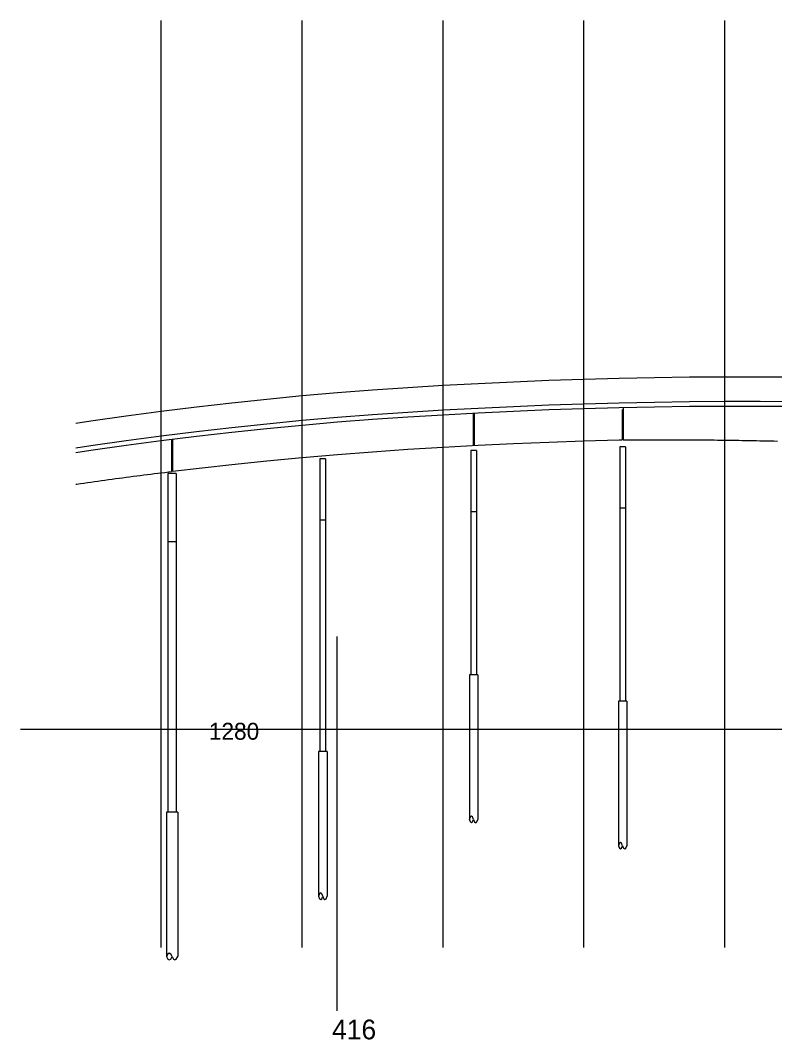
# Model space of a CAD drawing. Extents: x 2144454 to 2150191, y 137247 to 142100.
# Drawn here: x 2144454 to 2144990, y 137323 to 138047 of the extents above; entities that cross this region are included whole.
import ezdxf

# ---------------------------------------------------------------- set-up
doc = ezdxf.new("R2010")
doc.units = 0
for name, color, linetype in [('FinGrade', 7, 'Continuous'), ('PR_Bridge', 7, 'Continuous'), ('PR_Bridge_Pier', 7, 'Continuous'), ('XSEC_Section_Grid_Major', 7, 'Continuous')]:
    doc.layers.add(name, color=color, linetype=linetype)

msp = doc.modelspace()

# ---------------------------------------------------------------- linework, layer by layer
at = {"layer": 'Defpoints'}
for p, q in [((2144679.13, 137343.65), (2144679.13, 137609.38)), ((2144454.23, 137543.65), (2145154.23, 137543.65)), ((2144590.07, 137543.65), (2144690.59, 137543.65))]:
    msp.add_line(p, q, dxfattribs=at)
at = {"layer": 'FinGrade'}
for p, q in [((2144829.23, 137773.75), (2144854.23, 137774.6)), ((2144854.23, 137774.6), (2144879.23, 137775.28)), ((2144879.23, 137775.28), (2144904.23, 137775.79)), ((2144904.23, 137775.79), (2144929.23, 137776.13)), ((2144929.23, 137776.13), (2144954.23, 137776.3)), ((2144954.23, 137776.3), (2144979.23, 137776.3)), ((2144979.23, 137776.3), (2145004.23, 137776.13)), ((2144679.23, 137764.98), (2144704.23, 137766.9)), ((2144704.23, 137766.9), (2144729.23, 137768.62)), ((2144729.23, 137768.62), (2144754.23, 137770.16)), ((2144754.23, 137770.16), (2144779.23, 137771.53)), ((2144779.23, 137771.53), (2144804.23, 137772.72)), ((2144804.23, 137772.72), (2144829.23, 137773.75)), ((2144604.23, 137757.81), (2144629.23, 137760.44)), ((2144629.23, 137760.44), (2144654.23, 137762.83)), ((2144654.23, 137762.83), (2144679.23, 137764.98)), ((2144554.23, 137751.86), (2144579.23, 137754.95)), ((2144579.23, 137754.95), (2144604.23, 137757.81)), ((2144504.23, 137744.94), (2144529.23, 137748.52)), ((2144529.23, 137748.52), (2144554.23, 137751.86)), ((2144493.6, 137743.35), (2144504.23, 137744.94))]:
    msp.add_line(p, q, dxfattribs=at)
at = {"layer": 'PR_Bridge'}
for p, q in [((2144754.23, 137787.66), (2144779.23, 137789.03)), ((2144779.23, 137789.03), (2144804.23, 137790.22)), ((2144804.23, 137790.22), (2144829.23, 137791.25)), ((2144829.23, 137791.25), (2144854.23, 137792.1)), ((2144854.23, 137792.1), (2144879.23, 137792.78)), ((2144879.23, 137792.78), (2144904.23, 137793.29)), ((2144904.23, 137793.29), (2144929.23, 137793.63)), ((2144929.23, 137793.63), (2144954.23, 137793.8)), ((2144954.23, 137793.8), (2144979.23, 137793.8)), ((2144979.23, 137793.8), (2145004.23, 137793.63)), ((2144654.23, 137780.33), (2144679.23, 137782.48)), ((2144679.23, 137782.48), (2144704.23, 137784.4)), ((2144704.23, 137784.4), (2144729.23, 137786.12)), ((2144729.23, 137786.12), (2144754.23, 137787.66)), ((2144579.23, 137772.45), (2144604.23, 137775.31)), ((2144604.23, 137775.31), (2144629.23, 137777.94)), ((2144629.23, 137777.94), (2144654.23, 137780.33)), ((2144529.23, 137766.02), (2144554.23, 137769.36)), ((2144554.23, 137769.36), (2144579.23, 137772.45)), ((2144729.23, 137765.29), (2144754.23, 137766.83)), ((2144754.23, 137766.83), (2144779.23, 137768.2)), ((2144775.55, 137768.08), (2144775.55, 137744.99)), ((2144776.22, 137768.02), (2144776.22, 137745.03)), ((2144779.23, 137768.2), (2144804.23, 137769.39)), ((2144804.23, 137769.39), (2144829.23, 137770.42)), ((2144829.23, 137770.42), (2144854.23, 137771.27)), ((2144854.23, 137771.27), (2144879.23, 137771.95)), ((2144879.23, 137771.95), (2144904.23, 137772.46)), ((2144881.34, 137770.6), (2144881.34, 137748.94)), ((2144882.01, 137772), (2144882.01, 137748.97)), ((2144904.23, 137772.46), (2144929.23, 137772.79)), ((2144929.23, 137772.79), (2144954.23, 137772.96)), ((2144954.23, 137772.96), (2144979.23, 137772.96)), ((2144979.23, 137772.96), (2145004.23, 137772.79)), ((2144493.6, 137760.85), (2144504.23, 137762.44)), ((2144504.23, 137762.44), (2144529.23, 137766.02)), ((2144629.23, 137757.11), (2144654.23, 137759.49)), ((2144654.23, 137759.49), (2144679.23, 137761.65)), ((2144679.23, 137761.65), (2144704.23, 137763.57)), ((2144704.23, 137763.57), (2144729.23, 137765.29)), ((2144579.23, 137751.62), (2144604.23, 137754.48)), ((2144604.23, 137754.48), (2144629.23, 137757.11)), ((2144504.23, 137741.61), (2144529.23, 137745.19)), ((2144529.23, 137745.19), (2144554.23, 137748.52)), ((2144554.23, 137748.52), (2144579.23, 137751.62)), ((2144561.55, 137749.42), (2144561.55, 137726.46)), ((2144562.22, 137749.51), (2144562.22, 137726.54)), ((2144754.23, 137743.83), (2144779.23, 137745.19)), ((2144779.23, 137745.19), (2144804.23, 137746.39)), ((2144804.23, 137746.39), (2144829.23, 137747.41)), ((2144829.23, 137747.41), (2144854.23, 137748.26)), ((2144854.23, 137748.26), (2144879.23, 137748.94)), ((2144879.23, 137748.94), (2144881.34, 137748.99)), ((2144493.6, 137740.02), (2144504.23, 137741.61)), ((2144654.23, 137736.49), (2144679.23, 137738.65)), ((2144679.23, 137738.65), (2144704.23, 137740.57)), ((2144704.23, 137740.57), (2144729.23, 137742.28)), ((2144729.23, 137742.28), (2144754.23, 137743.83)), ((2144562.22, 137726.67), (2144604.23, 137731.48)), ((2144604.23, 137731.48), (2144629.23, 137734.1)), ((2144629.23, 137734.1), (2144654.23, 137736.49))]:
    msp.add_line(p, q, dxfattribs=at)
for points in [[(2144882.01, 137748.97), (2144884.14, 137748.98), (2144886.63, 137749), (2144889.13, 137749.02), (2144891.63, 137749.03), (2144894.13, 137749.04), (2144896.63, 137749.05), (2144899.13, 137749.06), (2144901.63, 137749.07), (2144904.13, 137749.07), (2144906.63, 137749.08), (2144909.13, 137749.08), (2144911.63, 137749.08), (2144914.13, 137749.08), (2144916.63, 137749.07), (2144919.12, 137749.06), (2144921.62, 137749.06), (2144924.12, 137749.05), (2144926.62, 137749.04), (2144929.12, 137749.02), (2144931.62, 137749.01), (2144934.12, 137748.99), (2144936.62, 137748.97), (2144939.12, 137748.95), (2144941.62, 137748.93), (2144944.12, 137748.9), (2144946.62, 137748.88), (2144949.11, 137748.85), (2144951.61, 137748.82), (2144954.11, 137748.79), (2144956.61, 137748.75), (2144959.11, 137748.72), (2144961.61, 137748.68), (2144964.11, 137748.64), (2144966.61, 137748.6), (2144969.11, 137748.56), (2144971.61, 137748.51), (2144974.11, 137748.47), (2144976.61, 137748.42), (2144979.1, 137748.37), (2144981.6, 137748.32), (2144984.1, 137748.26), (2144986.6, 137748.21), (2144989.1, 137748.15), (2144991.6, 137748.09)], [(2144493.6, 137717.51), (2144494.29, 137717.61), (2144496.79, 137717.97), (2144499.29, 137718.33), (2144501.79, 137718.69), (2144504.28, 137719.04), (2144506.78, 137719.39), (2144509.28, 137719.74), (2144511.78, 137720.09), (2144514.28, 137720.43), (2144516.78, 137720.77), (2144519.28, 137721.11), (2144521.78, 137721.44), (2144524.28, 137721.78), (2144526.77, 137722.11), (2144529.27, 137722.44), (2144531.77, 137722.76), (2144534.27, 137723.09), (2144536.77, 137723.41), (2144539.27, 137723.73), (2144541.77, 137724.05), (2144544.27, 137724.36), (2144546.77, 137724.67), (2144549.26, 137724.98), (2144551.76, 137725.29), (2144554.26, 137725.59), (2144556.76, 137725.89), (2144559.26, 137726.19), (2144561.55, 137726.46)]]:
    msp.add_lwpolyline(points, dxfattribs=at)
at = {"layer": 'PR_Bridge_Pier'}
for p, q in [((2144773.89, 137741.47), (2144773.89, 137582.15)), ((2144777.89, 137741.47), (2144773.89, 137741.47)), ((2144777.89, 137741.47), (2144777.89, 137582.15)), ((2144883.68, 137743.98), (2144879.68, 137743.98)), ((2144879.68, 137743.98), (2144879.68, 137563.54)), ((2144883.68, 137743.98), (2144883.68, 137563.54)), ((2144666.89, 137735.43), (2144666.89, 137527.67)), ((2144670.89, 137735.43), (2144666.89, 137735.43)), ((2144670.89, 137735.43), (2144666.89, 137735.43)), ((2144670.89, 137735.43), (2144670.89, 137527.67)), ((2144564.89, 137725.02), (2144558.89, 137725.02)), ((2144558.89, 137725.02), (2144558.89, 137484.83)), ((2144564.89, 137725.02), (2144564.89, 137484.83)), ((2144666.89, 137721.88), (2144666.89, 137527.67)), ((2144670.89, 137721.88), (2144670.89, 137527.67)), ((2144777.89, 137697.91), (2144773.89, 137697.91)), ((2144883.68, 137700.43), (2144879.68, 137700.43)), ((2144670.89, 137691.88), (2144666.89, 137691.88)), ((2144670.89, 137691.88), (2144666.89, 137691.88)), ((2144564.89, 137676.47), (2144558.89, 137676.47)), ((2144772.89, 137582.15), (2144772.89, 137479.56)), ((2144778.89, 137582.15), (2144772.89, 137582.15)), ((2144778.89, 137582.15), (2144778.89, 137479.56)), ((2144884.68, 137563.54), (2144878.68, 137563.54)), ((2144878.68, 137563.54), (2144878.68, 137460.95)), ((2144884.68, 137563.54), (2144884.68, 137460.95)), ((2144671.89, 137527.67), (2144665.89, 137527.67)), ((2144665.89, 137527.67), (2144665.89, 137425.08)), ((2144671.89, 137527.67), (2144665.89, 137527.67)), ((2144665.89, 137527.67), (2144665.89, 137425.08)), ((2144671.89, 137527.67), (2144671.89, 137425.08)), ((2144671.89, 137527.67), (2144671.89, 137425.08)), ((2144557.89, 137484.83), (2144557.89, 137382.23)), ((2144565.89, 137484.83), (2144557.89, 137484.83)), ((2144565.89, 137484.83), (2144565.89, 137382.23))]:
    msp.add_line(p, q, dxfattribs=at)
for centre, major_axis, start_param, end_param in [((2144774.39, 137468.67), (0, 13.23), 5.678607, 6.887764), ((2144774.39, 137490.44), (0, 13.23), 2.537014, 3.746171), ((2144777.39, 137490.32), (0, 13.11), 2.534234, 3.748951), ((2144880.18, 137450.06), (0, 13.23), 5.678607, 6.887764), ((2144880.18, 137471.83), (0, 13.23), 2.537014, 3.746171), ((2144883.18, 137471.71), (0, 13.11), 2.534234, 3.748951), ((2144667.39, 137414.19), (0, 13.23), 5.678607, 6.887764), ((2144667.39, 137414.19), (0, 13.23), 5.678607, 6.887764), ((2144667.39, 137435.96), (0, 13.23), 2.537014, 3.746171), ((2144667.39, 137435.96), (0, 13.23), 2.537014, 3.746171), ((2144670.39, 137435.84), (0, 13.11), 2.534234, 3.748951), ((2144670.39, 137435.84), (0, 13.11), 2.534234, 3.748951), ((2144559.89, 137362.08), (0, 22.5), 5.822593, 6.743777), ((2144559.89, 137402.39), (0, 22.5), 2.681001, 3.602185), ((2144563.89, 137402.39), (0, 22.5), 2.681001, 3.602185)]:
    msp.add_ellipse(centre, major_axis=major_axis, ratio=0.2, start_param=start_param, end_param=end_param, dxfattribs=at)
at = {"layer": 'XSEC_Section_Grid_Major'}
for p, q in [((2144554.23, 137388.65), (2144554.23, 138046.65)), ((2144654.23, 137388.65), (2144654.23, 138046.65)), ((2144754.23, 137388.65), (2144754.23, 138046.65)), ((2144854.23, 137388.65), (2144854.23, 138046.65)), ((2144954.23, 137388.65), (2144954.23, 138046.65))]:
    msp.add_line(p, q, dxfattribs=at)

# ---------------------------------------------------------------- texts
at = {"layer": 'Defpoints'}
for s, height, p in [('1280', 12, (2144588.03, 137536.15)), ('416', 14, (2144675.51, 137323.51))]:
    msp.add_text(s, height=height, dxfattribs=at).set_placement(p)

doc.saveas('drawing.dxf')
